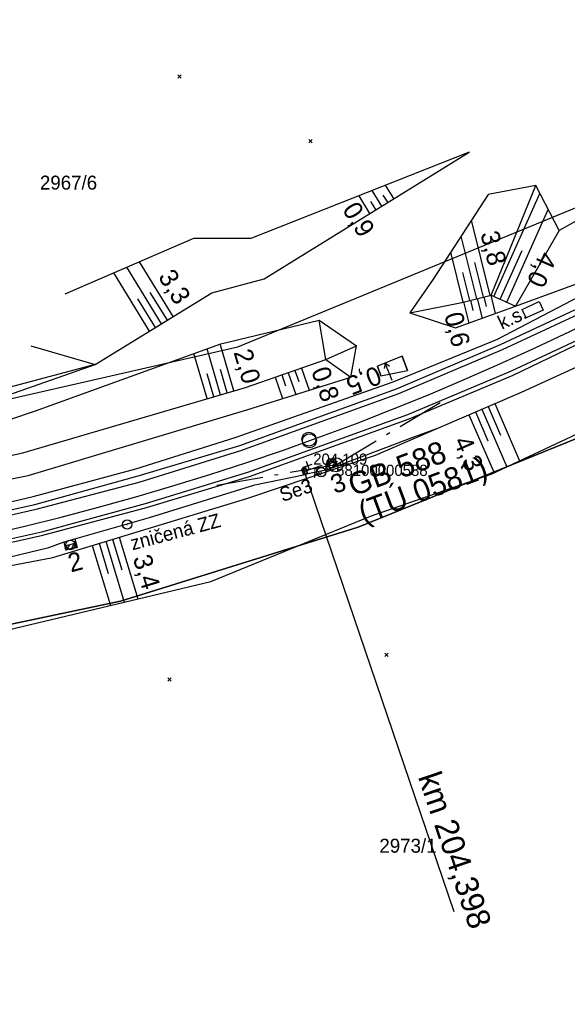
# Model space of a CAD drawing. Extents: x -800194 to -799078, y -1007177 to -1006597.
# Drawn here: x -799583.1 to -799524.3, y -1007037.9 to -1006933.3 of the extents above; entities that cross this region are included whole.
import ezdxf

# ---------------------------------------------------------------- set-up
doc = ezdxf.new("R2010")
doc.units = 0
for name, color, linetype in [('02_Osa_koleje', 7, 'Continuous'), ('_Vrstva 7 - Přesunutá', 7, 'Continuous'), ('Vrstva 11', 7, 'Continuous'), ('Vrstva 12', 7, 'Continuous'), ('Vrstva 13', 7, 'Continuous'), ('Vrstva 25', 7, 'Continuous'), ('Vrstva 4', 7, 'Continuous'), ('Vrstva 48', 7, 'Continuous'), ('Vrstva 49', 7, 'Continuous'), ('Vrstva 50', 7, 'Continuous'), ('Vrstva 53', 7, 'Continuous'), ('Vrstva 55', 7, 'Continuous'), ('Vrstva 57', 7, 'Continuous'), ('Vrstva 6', 7, 'Continuous'), ('Vrstva 60', 7, 'Continuous'), ('Vrstva 61', 7, 'Continuous'), ('Vrstva 63', 7, 'Continuous'), ('Vrstva 7', 7, 'Continuous')]:
    doc.layers.add(name, color=color, linetype=linetype)

msp = doc.modelspace()

# ---------------------------------------------------------------- linework, layer by layer
at = {"layer": '02_Osa_koleje'}
msp.add_arc((-799651.02, -1006703.89), 292, 255.6249, 308.2052, dxfattribs=at)
at = {"layer": '_Vrstva 7 - Přesunutá'}
msp.add_circle((-799551.96, -1006978.57), 0.75, dxfattribs=at)
at = {"layer": 'Vrstva 11'}
for p, q in [((-799549.13, -1006980.79), (-799550.08, -1006981.14)), ((-799549.87, -1006981.38), (-799549.69, -1006981)), ((-799549.49, -1006981.45), (-799549.2, -1006980.81)), ((-799577.11, -1006989.6), (-799578.08, -1006989.86)), ((-799577.53, -1006990.23), (-799577.18, -1006989.62)), ((-799577.9, -1006990.13), (-799577.69, -1006989.76))]:
    msp.add_line(p, q, dxfattribs=at)
for centre in [(-799549.6, -1006980.96), (-799577.6, -1006989.73)]:
    msp.add_circle(centre, 0.503, dxfattribs=at)
for centre, start, end in [((-799549.6, -1006980.96), 200.5311, 20.5311), ((-799577.6, -1006989.73), 194.9449, 14.9449)]:
    msp.add_arc(centre, 0.503, start, end, dxfattribs=at)
at = {"layer": 'Vrstva 12'}
for p, q in [((-799552.8, -1006981.61), (-799552.75, -1006981.62)), ((-799552.57, -1006982.18), (-799552.61, -1006982.23)), ((-799552.38, -1006981.51), (-799552.33, -1006981.46)), ((-799552.2, -1006982.07), (-799552.13, -1006982.09))]:
    msp.add_line(p, q, dxfattribs=at)
for points in [[(-799550.23, -1006981.08), (-799550.03, -1006981.64), (-799548.93, -1006981.25), (-799549.17, -1006980.59), (-799550.23, -1006981.08)], [(-799550.23, -1006981.08), (-799550.03, -1006981.64), (-799548.93, -1006981.25), (-799549.17, -1006980.59)], [(-799548.93, -1006981.25), (-799548.93, -1006981.25)], [(-799552.33, -1006981.46), (-799552.8, -1006981.61), (-799552.61, -1006982.23), (-799552.13, -1006982.09), (-799552.33, -1006981.46)], [(-799552.75, -1006981.62), (-799552.38, -1006981.51), (-799552.2, -1006982.07), (-799552.57, -1006982.18), (-799552.75, -1006981.62)], [(-799550.03, -1006981.64), (-799550.03, -1006981.64)], [(-799577.13, -1006989.11), (-799576.89, -1006990.02), (-799578.08, -1006990.31), (-799578.26, -1006989.41)], [(-799576.94, -1006990.02), (-799578.06, -1006990.29), (-799578.26, -1006989.41), (-799577.13, -1006989.11), (-799576.94, -1006990.02)], [(-799578.06, -1006990.29), (-799578.08, -1006990.31)], [(-799576.94, -1006990.02), (-799576.89, -1006990.02)]]:
    msp.add_lwpolyline(points, dxfattribs=at)
at = {"layer": 'Vrstva 13'}
for p, q in [((-799542.02, -1006969.49), (-799544.64, -1006970.55)), ((-799543.09, -1006972.09), (-799543.84, -1006970.23))]:
    msp.add_line(p, q, dxfattribs=at)
for points in [[(-799544.28, -1006971.59), (-799541.43, -1006971.03), (-799542.01, -1006969.49), (-799544.64, -1006970.55), (-799544.28, -1006971.59)], [(-799542.01, -1006969.49), (-799542.02, -1006969.49), (-799541.43, -1006971.03)], [(-799544.28, -1006971.59), (-799544.64, -1006970.55), (-799544.64, -1006970.55)], [(-799543.38, -1006970.58), (-799543.84, -1006970.23), (-799543.94, -1006970.81)]]:
    msp.add_lwpolyline(points, dxfattribs=at)
at = {"layer": 'Vrstva 25'}
msp.add_lwpolyline([(-799528.69, -1006965.38), (-799529.12, -1006964.48), (-799527.31, -1006963.63), (-799526.88, -1006964.54), (-799528.69, -1006965.38)], dxfattribs=at)
at = {"layer": 'Vrstva 4'}
for points in [[(-799766.32, -1006970.57), (-799760.95, -1006972.54), (-799747.64, -1006977.46), (-799730.55, -1006982.98), (-799710.07, -1006987.58), (-799704.73, -1006988.35), (-799693, -1006990.37), (-799682.43, -1006991.64), (-799671.27, -1006992.62), (-799659.31, -1006993.03), (-799648.69, -1006993.12), (-799637.4, -1006992.7), (-799625.91, -1006992.18), (-799614.96, -1006990.83), (-799603.91, -1006989.31), (-799592.73, -1006987.17), (-799581.6, -1006984.55), (-799570.58, -1006981.6), (-799559.91, -1006978.22), (-799542.96, -1006972.25), (-799531.79, -1006967.66), (-799521.29, -1006962.19), (-799511.24, -1006957.13)], [(-799779.68, -1006964.3), (-799766.32, -1006970.57), (-799761.25, -1006973.18), (-799747.77, -1006978.42), (-799730.77, -1006983.8), (-799710.33, -1006988.71), (-799704.92, -1006989.74), (-799693.13, -1006991.41), (-799682.58, -1006992.93), (-799671.33, -1006993.88), (-799659.36, -1006994.45), (-799648.66, -1006994.5), (-799637.23, -1006994.13), (-799626.07, -1006993.34), (-799614.79, -1006992.17), (-799603.67, -1006990.51), (-799592.47, -1006988.45), (-799581.28, -1006985.92), (-799570.22, -1006983), (-799559.3, -1006979.61), (-799542.38, -1006973.48), (-799531.24, -1006968.77), (-799520.48, -1006963.76), (-799510.39, -1006958.54)], [(-799776.86, -1006969.09), (-799770.96, -1006971.65), (-799761.91, -1006975.65), (-799748.54, -1006980.78), (-799731.46, -1006986.21), (-799711.13, -1006991.05), (-799705.48, -1006992.16), (-799693.53, -1006994.08), (-799682.8, -1006995.38), (-799671.51, -1006996.32), (-799659.45, -1006996.85), (-799648.59, -1006996.95), (-799637.26, -1006996.57), (-799625.83, -1006995.77), (-799614.55, -1006994.59), (-799603.2, -1006992.95), (-799591.97, -1006990.86), (-799580.65, -1006988.34), (-799569.53, -1006985.31), (-799558.56, -1006981.95), (-799541.41, -1006975.74), (-799530.26, -1006971.07), (-799519.46, -1006966), (-799509.25, -1006960.72)], [(-799776.86, -1006969.09), (-799771.26, -1006971.98), (-799762.13, -1006976.09), (-799748.71, -1006981.29), (-799731.51, -1006986.35), (-799711.22, -1006991.46), (-799705.53, -1006992.59), (-799693.58, -1006994.54), (-799682.85, -1006995.9), (-799671.5, -1006996.81), (-799659.56, -1006997.36), (-799648.62, -1006997.34), (-799637.28, -1006997.07), (-799625.83, -1006996.3), (-799614.43, -1006995.11), (-799603.18, -1006993.47), (-799591.85, -1006991.26), (-799580.56, -1006988.7), (-799569.45, -1006985.75), (-799558.39, -1006982.39), (-799541.27, -1006976.23), (-799530.1, -1006971.51), (-799519.4, -1006966.36), (-799509.09, -1006961.13)], [(-799779.01, -1006963.02), (-799770.63, -1006967.94), (-799766.32, -1006970.57), (-799761.02, -1006972.82), (-799747.75, -1006977.97), (-799730.72, -1006983.27), (-799710.2, -1006988.11), (-799704.77, -1006989.18), (-799693.07, -1006990.96), (-799682.55, -1006992.24), (-799671.27, -1006993.22), (-799659.39, -1006993.77), (-799648.66, -1006993.82), (-799637.39, -1006993.53), (-799625.77, -1006992.73), (-799614.9, -1006991.54), (-799603.91, -1006989.96), (-799592.57, -1006987.89), (-799581.42, -1006985.42), (-799570.33, -1006982.33), (-799559.43, -1006979.07), (-799542.6, -1006973.01), (-799531.45, -1006968.25), (-799520.74, -1006963.21)], [(-799683.1, -1006997.41), (-799671.67, -1006998.28), (-799659.52, -1006998.78), (-799648.52, -1006998.59), (-799637.01, -1006998.22), (-799625.7, -1006997.42), (-799614.69, -1006996.42), (-799603.02, -1006994.65), (-799591.63, -1006992.87), (-799579.9, -1006990.02), (-799578.26, -1006989.41), (-799577.13, -1006989.11), (-799569.11, -1006986.79), (-799557.83, -1006983.31), (-799552.61, -1006982.23), (-799552.13, -1006982.09), (-799550.03, -1006981.64), (-799548.93, -1006981.25), (-799540.64, -1006978.12), (-799538.19, -1006977.21), (-799529.22, -1006973.34), (-799517.86, -1006968.17)]]:
    msp.add_lwpolyline(points, dxfattribs=at)
at = {"layer": 'Vrstva 48'}
for p, q in [((-799544.18, -1006953.37), (-799545.21, -1006951.7)), ((-799542.91, -1006952.58), (-799543.8, -1006951.14)), ((-799532.16, -1006963.07), (-799527.23, -1006952.03)), ((-799545.46, -1006954.16), (-799546.63, -1006952.26)), ((-799544.82, -1006953.76), (-799545.37, -1006952.87)), ((-799543.54, -1006952.97), (-799544.03, -1006952.19)), ((-799530.79, -1006963.68), (-799526.35, -1006953.73)), ((-799532.55, -1006962.96), (-799534.57, -1006954.9)), ((-799534.01, -1006963.32), (-799535.68, -1006956.62)), ((-799531.48, -1006963.38), (-799529.13, -1006958.13)), ((-799566.56, -1006965.23), (-799570.17, -1006959.35)), ((-799535.46, -1006963.68), (-799536.8, -1006958.34)), ((-799567.84, -1006966.02), (-799571.56, -1006959.95)), ((-799533.28, -1006963.14), (-799534.2, -1006959.45)), ((-799569.11, -1006966.8), (-799572.95, -1006960.55)), ((-799534.73, -1006963.5), (-799535.49, -1006960.49)), ((-799568.48, -1006966.41), (-799570.36, -1006963.33)), ((-799567.2, -1006965.63), (-799569.03, -1006962.64)), ((-799534.69, -1006963.49), (-799534.41, -1006964.58)), ((-799533.96, -1006963.31), (-799533.43, -1006965.41)), ((-799533.23, -1006963.13), (-799532.98, -1006964.14)), ((-799532.5, -1006962.94), (-799532.02, -1006964.9)), ((-799535.41, -1006963.67), (-799534.85, -1006965.93)), ((-799561.49, -1006973.63), (-799562.94, -1006968.7)), ((-799560.05, -1006973.21), (-799561.52, -1006968.18)), ((-799562.93, -1006974.05), (-799564.35, -1006969.21)), ((-799552.81, -1006970.76), (-799551.98, -1006973.15)), ((-799562.21, -1006973.84), (-799562.93, -1006971.4)), ((-799560.77, -1006973.42), (-799561.5, -1006970.93)), ((-799555.64, -1006971.75), (-799554.84, -1006974.05)), ((-799554.93, -1006971.5), (-799554.53, -1006972.66)), ((-799554.23, -1006971.26), (-799553.41, -1006973.6)), ((-799553.52, -1006971.01), (-799553.11, -1006972.19)), ((-799532.77, -1006974.88), (-799531.44, -1006977.96)), ((-799532.08, -1006974.58), (-799529.43, -1006980.73)), ((-799534.84, -1006975.77), (-799532.14, -1006982)), ((-799534.15, -1006975.47), (-799532.81, -1006978.58)), ((-799533.46, -1006975.17), (-799530.78, -1006981.37)), ((-799574.53, -1006989.58), (-799573.54, -1006992.82)), ((-799573.81, -1006989.36), (-799571.83, -1006995.89)), ((-799573.09, -1006989.15), (-799572.1, -1006992.43)), ((-799572.38, -1006988.93), (-799570.37, -1006995.54)), ((-799575.25, -1006989.8), (-799573.29, -1006996.24))]:
    msp.add_line(p, q, dxfattribs=at)
at = {"layer": 'Vrstva 49'}
for p, q in [((-799566.06, -1006939.3), (-799565.71, -1006939.65)), ((-799566.06, -1006939.65), (-799565.71, -1006939.3)), ((-799552.02, -1006946.24), (-799551.67, -1006946.59)), ((-799552.02, -1006946.59), (-799551.67, -1006946.24)), ((-799525.18, -1006956), (-799529.84, -1006964.11)), ((-799550.2, -1006969.86), (-799546.89, -1006968.39)), ((-799550.2, -1006969.86), (-799547.5, -1006971.75)), ((-799543.85, -1007001.37), (-799543.5, -1007001.72)), ((-799543.85, -1007001.72), (-799543.5, -1007001.37)), ((-799567.13, -1007004.01), (-799566.78, -1007004.36)), ((-799567.13, -1007004.36), (-799566.78, -1007004.01))]:
    msp.add_line(p, q, dxfattribs=at)
for points in [[(-799581.84, -1006968.38), (-799574.95, -1006970.38), (-799562.43, -1006962.7), (-799556.81, -1006961.17), (-799534.83, -1006947.59)], [(-799534.83, -1006947.59), (-799558.24, -1006956.85), (-799564.4, -1006956.87), (-799578.21, -1006962.82)], [(-799510.22, -1006947.62), (-799525.18, -1006956), (-799527.68, -1006951.16), (-799532.77, -1006952.14), (-799538.67, -1006961.22), (-799541.2, -1006964.83)], [(-799541.2, -1006964.83), (-799535.61, -1006963.72), (-799532.47, -1006962.94), (-799527.68, -1006951.16)], [(-799532.47, -1006962.94), (-799529.84, -1006964.11), (-799521.84, -1006961.19), (-799512.05, -1006955.96)], [(-799710.32, -1006994.82), (-799708.87, -1006995.03), (-799692.77, -1006997.82), (-799673.3, -1007001.05), (-799659.56, -1007000.48), (-799648.46, -1007000.69), (-799625.45, -1006999.1), (-799615.7, -1006997.51), (-799614.57, -1006997.35), (-799602.96, -1006995.58), (-799579.5, -1006991.09), (-799558.66, -1006984.76), (-799544.86, -1006980.11), (-799538.19, -1006977.21), (-799529.22, -1006973.34), (-799517.86, -1006968.17), (-799516.56, -1006967), (-799515.53, -1006966.51), (-799507.82, -1006962.78)], [(-799541.2, -1006964.83), (-799536.29, -1006966.45), (-799529.84, -1006964.11)], [(-799621.79, -1006985.66), (-799603.52, -1006982.85), (-799581.35, -1006975.36), (-799561.47, -1006968.16), (-799550.92, -1006965.64), (-799546.89, -1006968.39)], [(-799619.91, -1006986.72), (-799603.2, -1006984.32), (-799582.71, -1006979.85), (-799558.8, -1006972.84), (-799550.2, -1006969.86), (-799550.92, -1006965.64)], [(-799621.79, -1006985.66), (-799621.59, -1006987.7), (-799603.12, -1006986.49), (-799582.14, -1006982.3), (-799558.67, -1006975.25), (-799547.5, -1006971.75), (-799546.89, -1006968.39)], [(-799641.81, -1007006.94), (-799621, -1007006.24), (-799608.68, -1007003.52), (-799602.42, -1007004.97), (-799584.29, -1006998.85), (-799562.54, -1006993.68), (-799545.4, -1006986.65), (-799532.46, -1006982.15), (-799507.06, -1006970.25)], [(-799574.95, -1006970.38), (-799603.15, -1006977.91), (-799621.41, -1006980.87), (-799634.22, -1006983.56), (-799639.94, -1006987.57)], [(-799639.94, -1006987.57), (-799633.79, -1006986.38), (-799621.45, -1006982.97), (-799603.21, -1006980.3), (-799574.95, -1006970.38)]]:
    msp.add_lwpolyline(points, dxfattribs=at)
at = {"layer": 'Vrstva 50'}
msp.add_line((-799571.56, -1006987.58), (-799571.46, -1006987.55), dxfattribs=at)
msp.add_circle((-799571.51, -1006987.56), 0.5, dxfattribs=at)
at = {"layer": 'Vrstva 53'}
for points in [[(-799686.25, -1006963.73), (-799670.17, -1006962.64), (-799668.03, -1006961.74), (-799668, -1006962.02), (-799667.43, -1006981.06), (-799637.16, -1006982.06), (-799603.07, -1006978.39), (-799559.64, -1006968.48), (-799519.68, -1006952.01)], [(-799521.98, -1006977.8), (-799546.71, -1006987.83), (-799572.22, -1006995.8), (-799583.97, -1006998.26), (-799599.63, -1007001.65), (-799584.37, -1007069.36), (-799591.04, -1007071.48), (-799597.25, -1007073.58), (-799607.27, -1007078.7), (-799623.27, -1007096.82), (-799619.94, -1007099.79), (-799606.31, -1007085.7), (-799604.36, -1007100.23), (-799602.09, -1007115.59), (-799604.31, -1007116.28), (-799613.8, -1007119.26), (-799629.52, -1007122.44), (-799580.26, -1007176.65)]]:
    msp.add_lwpolyline(points, dxfattribs=at)
at = {"layer": 'Vrstva 55'}
for points in [[(-799667.43, -1006981.06), (-799637.16, -1006982.06), (-799603.07, -1006978.39), (-799559.64, -1006968.48), (-799519.68, -1006952.01)], [(-799599.63, -1007001.65), (-799583.97, -1006998.26), (-799572.22, -1006995.8), (-799546.71, -1006987.83), (-799521.98, -1006977.8), (-799495.25, -1006963.74), (-799489.22, -1006959.79), (-799487.22, -1006958.47)]]:
    msp.add_lwpolyline(points, dxfattribs=at)
at = {"layer": 'Vrstva 6'}
for p, q in [((-799550.61, -1006981.22), (-799552.49, -1006981.86)), ((-799552.65, -1006981.39), (-799552.33, -1006982.33)), ((-799536.43, -1007029.12), (-799552.52, -1006981.78))]:
    msp.add_line(p, q, dxfattribs=at)
at = {"layer": 'Vrstva 60'}
msp.add_line((-799549.09, -1006981.14), (-799549.09, -1006981.14), dxfattribs=at)
at = {"layer": 'Vrstva 63'}
for p, q in [((-799542.23, -1006977.03), (-799537.94, -1006974.46)), ((-799543.69, -1006977.9), (-799543.34, -1006977.69)), ((-799549.09, -1006981.14), (-799544.8, -1006978.57)), ((-799549.09, -1006981.14), (-799554.02, -1006981.99)), ((-799549.14, -1006981.15), (-799549.05, -1006981.12)), ((-799555.3, -1006982.21), (-799555.69, -1006982.28)), ((-799556.97, -1006982.5), (-799561.9, -1006983.36))]:
    msp.add_line(p, q, dxfattribs=at)
msp.add_circle((-799549.09, -1006981.14), 0.756, dxfattribs=at)
at = {"layer": 'Vrstva 7'}
for p, q in [((-799552.62, -1006981.39), (-799551.67, -1006981.07)), ((-799552.31, -1006980.76), (-799551.98, -1006981.7)), ((-799550.73, -1006981.95), (-799550.64, -1006981.92))]:
    msp.add_line(p, q, dxfattribs=at)
for centre, radius in [((-799552.01, -1006978.4), 0.75), ((-799550.69, -1006981.94), 0.5)]:
    msp.add_circle(centre, radius, dxfattribs=at)

# ---------------------------------------------------------------- texts
at = {"layer": 'Vrstva 11'}
for s, rotation, p in [('3', 20.5311, (-799549.23, -1006984.3)), ('2', 14.9449, (-799577.55, -1006992.71))]:
    msp.add_text(s, height=2, rotation=rotation, dxfattribs=at).set_placement(p)
at = {"layer": 'Vrstva 13'}
msp.add_text('0,5', height=2, rotation=202.0385, dxfattribs=at).set_placement((-799544.77, -1006970.49))
at = {"layer": 'Vrstva 25'}
msp.add_text('k.s.', height=1.5, rotation=25.0865, dxfattribs=at).set_placement((-799531.31, -1006966.67))
at = {"layer": 'Vrstva 48'}
for s, rotation, p in [('0,9', 301.724, (-799548.49, -1006953.74)), ('3,8', 284.0577, (-799533.63, -1006956.32)), ('4,0', 245.9384, (-799527.16, -1006958.11)), ('3,3', 301.5339, (-799568.24, -1006960.96)), ('0,6', 284.0577, (-799537.51, -1006965.05)), ('2,0', 286.3372, (-799560.11, -1006969.06)), ('0,8', 289.0997, (-799551.79, -1006971.05)), ('4,3', 293.3695, (-799536.54, -1006978.61)), ('3,4', 286.8948, (-799570.92, -1006991.15))]:
    msp.add_text(s, height=2, rotation=rotation, dxfattribs=at).set_placement(p)
at = {"layer": 'Vrstva 50'}
msp.add_text('zničená ZZ', height=1.5, rotation=14.9449, dxfattribs=at).set_placement((-799570.94, -1006990.34))
at = {"layer": 'Vrstva 57'}
for s, p in [('2967/6', (-799580.87, -1006951.61)), ('2973/1', (-799544.45, -1007022.79))]:
    msp.add_text(s, height=1.5, dxfattribs=at).set_placement(p)
at = {"layer": 'Vrstva 6'}
for s, height, rotation, p in [('  A A ', 1, 18.7608, (-799552.17, -1006982.81)), ('Se3', 1.5, 18.7608, (-799554.86, -1006985.15)), ('km 204,398', 2.5, 288.7608, (-799540.34, -1007014.64))]:
    msp.add_text(s, height=height, rotation=rotation, dxfattribs=at).set_placement(p)
at = {"layer": 'Vrstva 60'}
msp.add_text('58100000588', height=1.2, dxfattribs=at).set_placement((-799549.09, -1006982.34))
at = {"layer": 'Vrstva 61'}
msp.add_text('204.109', height=1.2, dxfattribs=at).set_placement((-799551.55, -1006981.14))
at = {"layer": 'Vrstva 63'}
for s, p in [('GB 588', (-799547.24, -1006984.56)), ('(TÚ 0581)', (-799546.15, -1006987.47))]:
    msp.add_text(s, height=2.4, rotation=20.5311, dxfattribs=at).set_placement(p)

doc.saveas('drawing.dxf')
